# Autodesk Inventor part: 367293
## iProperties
Created: 2006-06
Part Number: 367293
Document SubType Name: Modeling
Designer: I.Baliuc
Material: 8.8 vz
Description: Sperrzahnschraube
Density: 7.85 g/cm^3
Abmessung: M6 x 16
Author: T.Messerschmitt
Revision Number: 367293
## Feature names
1. Basis1
